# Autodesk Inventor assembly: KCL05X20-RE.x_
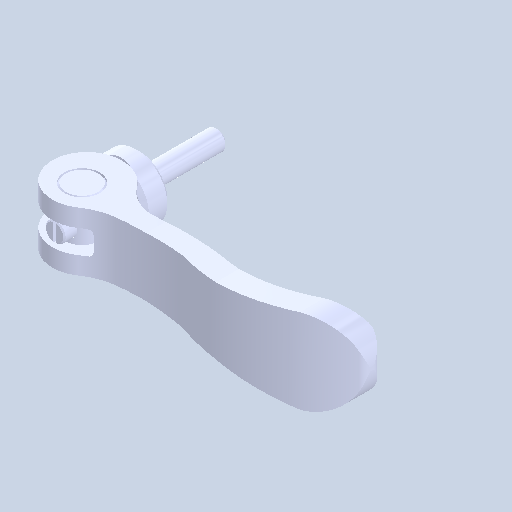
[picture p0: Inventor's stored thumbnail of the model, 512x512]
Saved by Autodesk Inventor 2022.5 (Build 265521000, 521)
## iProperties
Created: 2024-08
Part Number: KCL05X20-RE.x_
Document SubType Name: Assembly
Designer: ImaoCorp
Author: ImaoCorp
Sending System: SOLIDWORKS 2022-2022290
MC: AMD64
MC_MODEL: Intel64 Family 6 Model 60 Stepping 3, GenuineIntel
OS: Windows_NT
FRU: Parasolid Version 33.1, build 260,  4-25-2022
FORMAT: text
GUISE: transmit
KEY: FILEKCL05X20-RE.x_t
DATE: Thu Aug 29 10:48:58 2024
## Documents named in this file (5)
- Y:\5.更新分\2024年対応\1001_KCL\データ\kcl05x20-re\KCL05X20-RE.x_.iam
- Y:\5.更新分\2024年対応\1001_KCL\データ\kcl05x20-re\KCL05X20-RE_01.ipt
- Y:\5.更新分\2024年対応\1001_KCL\データ\kcl05x20-re\KCL05X20-RE_02.ipt
- Y:\5.更新分\2024年対応\1001_KCL\データ\kcl05x20-re\KCL05X20-RE_03.ipt
- Y:\5.更新分\2024年対応\1001_KCL\データ\kcl05x20-re\KCL05X20-RE_04.ipt
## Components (4 placed, 4 different names)
1. KCL05X20-RE_01
2. KCL05X20-RE_02
3. KCL05X20-RE_03
4. KCL05X20-RE_04
